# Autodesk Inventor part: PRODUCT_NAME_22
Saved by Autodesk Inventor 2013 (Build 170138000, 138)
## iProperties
Created: 2012-12
Part Number: PRODUCT_NAME_22
Material: Générique
Document SubType Name: Modeling
Designer: jost thierry
Density: 1 g/cm^3
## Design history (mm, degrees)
node "PRODUCT_NAME_221"
node "PRODUCT_NAME_22"
node "Base1"
